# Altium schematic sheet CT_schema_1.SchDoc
size 642 x 258 mm
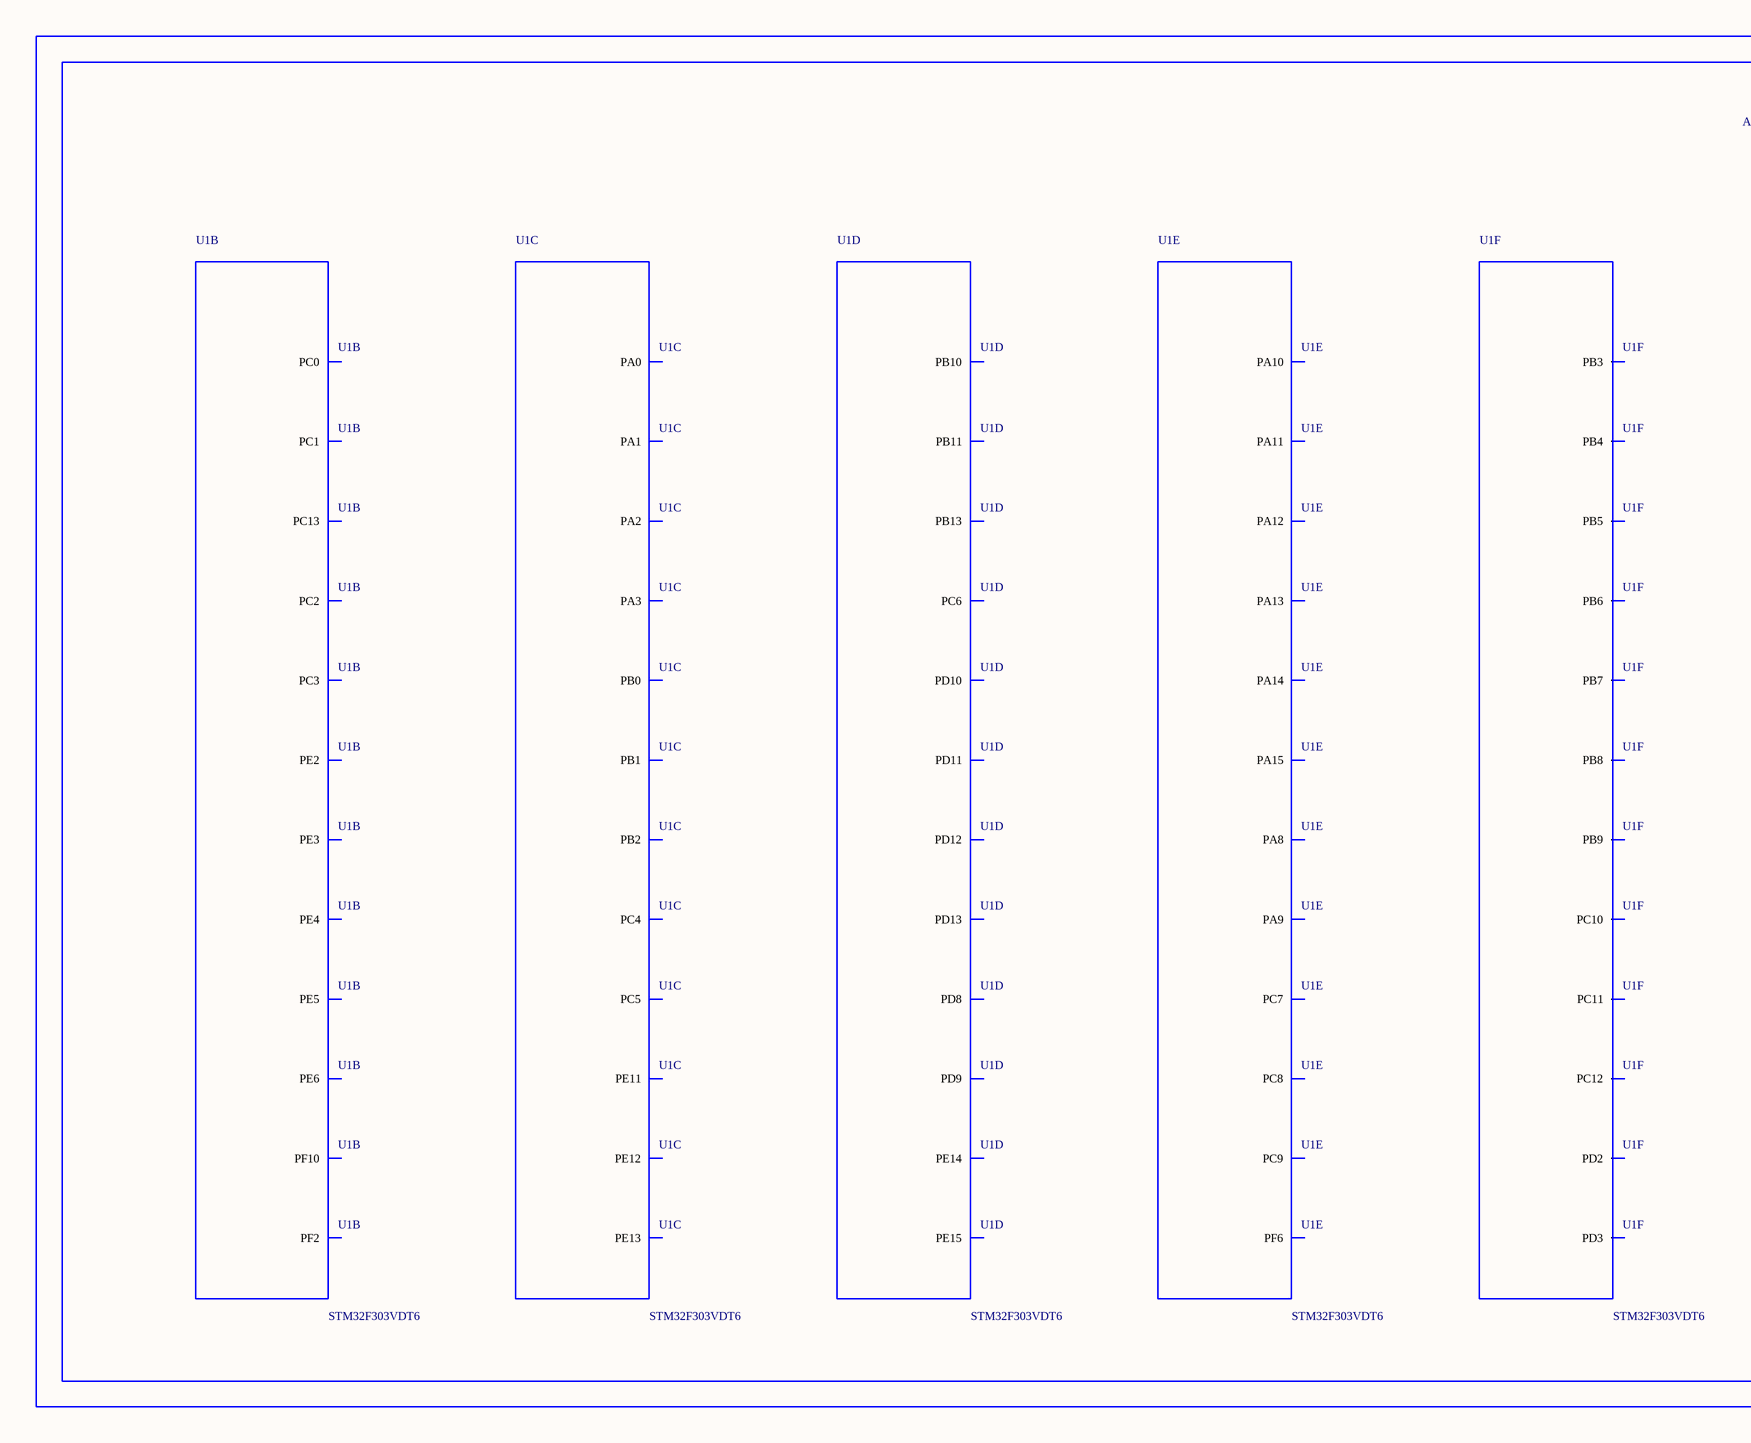
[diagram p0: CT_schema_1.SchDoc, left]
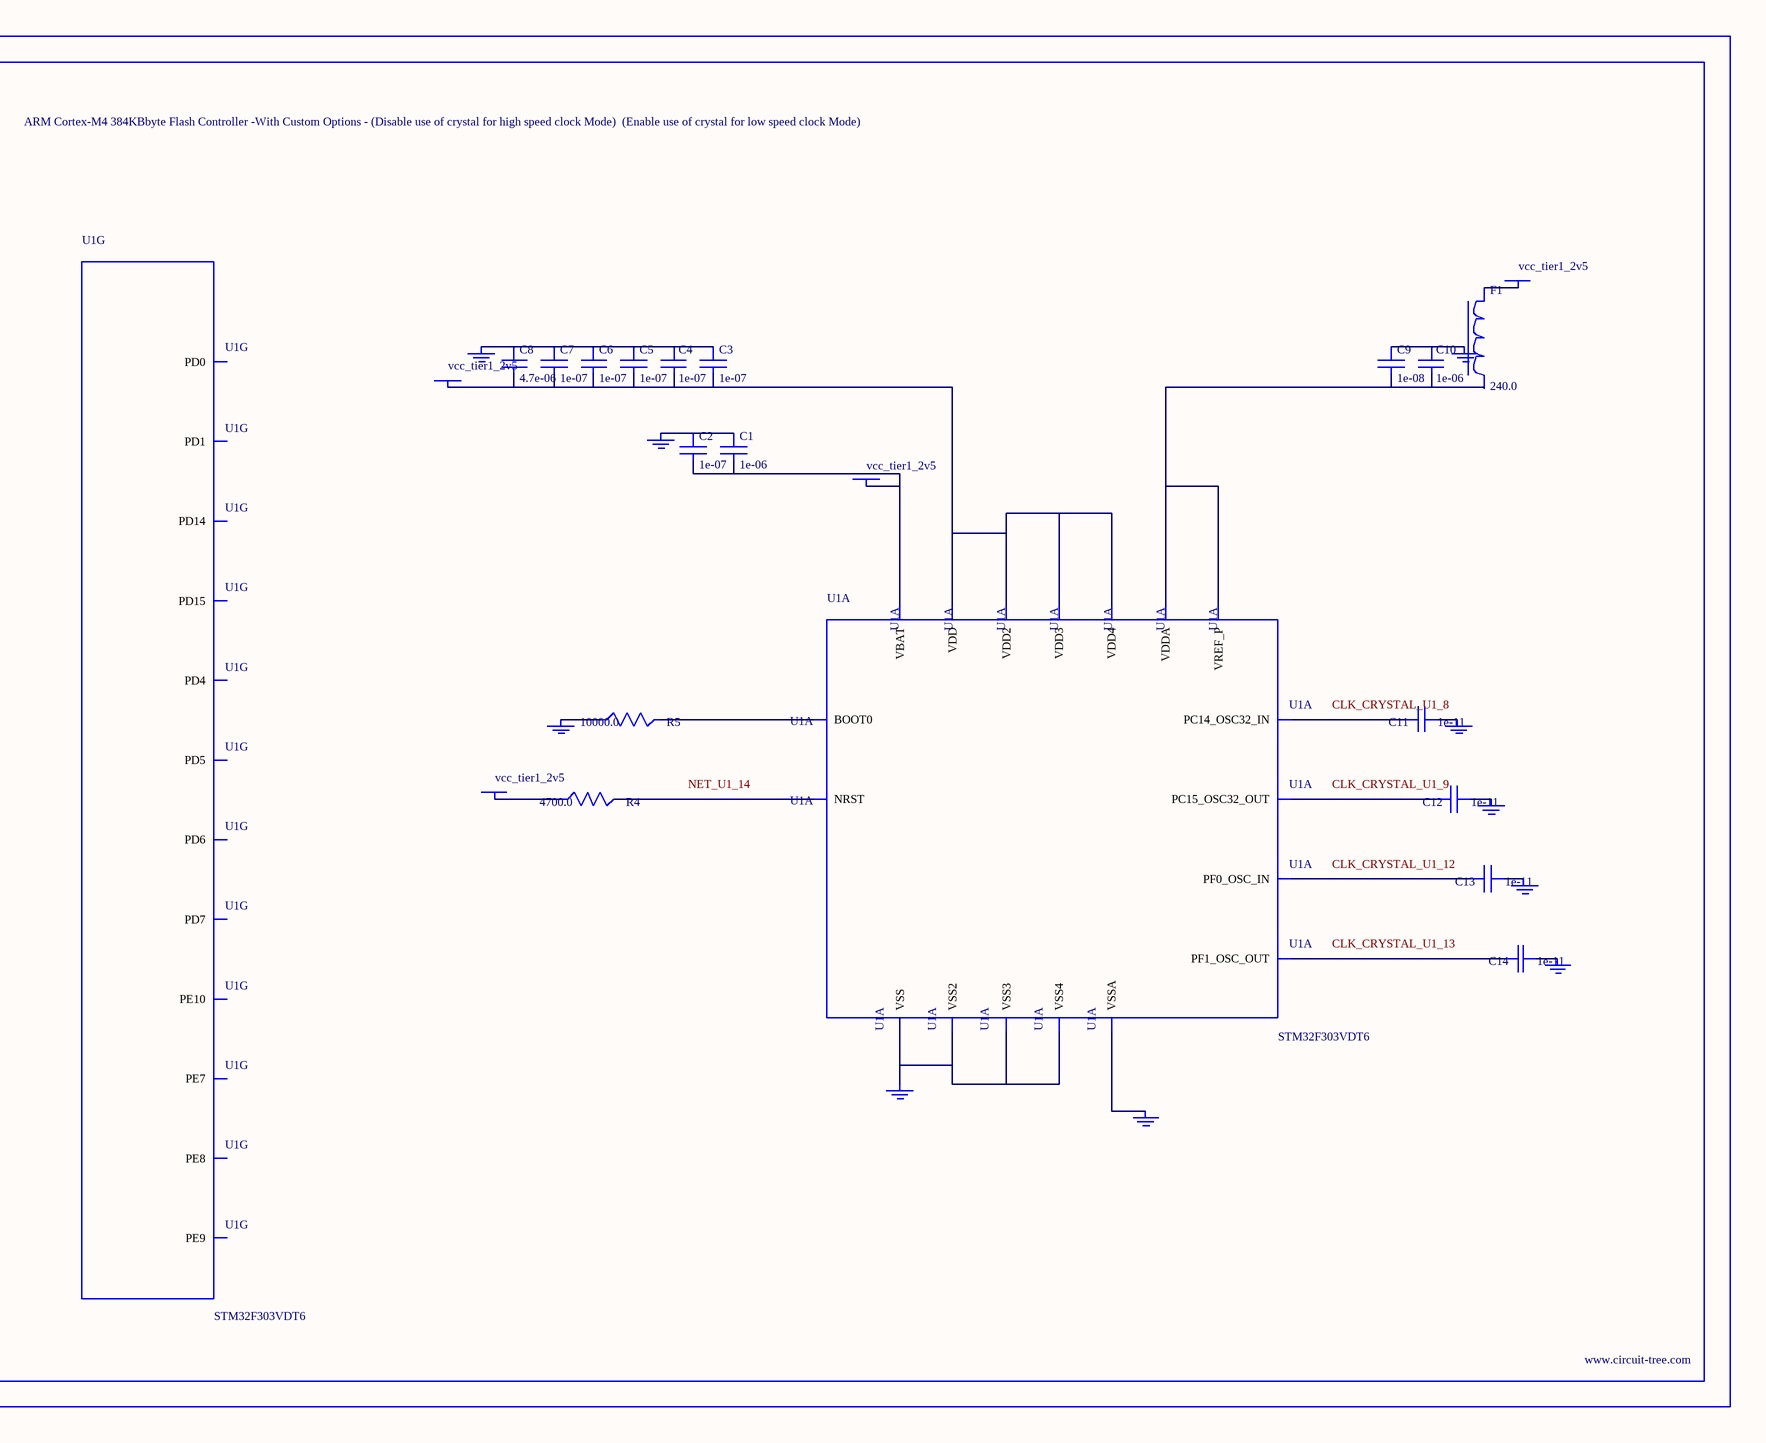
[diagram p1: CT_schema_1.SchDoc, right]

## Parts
BORDER0  (no value)
C1  1e-06  [C0603]
C2  1e-07  [C0603]
C3  1e-07  [C0603]
C4  1e-07  [C0603]
C5  1e-07  [C0603]
C6  1e-07  [C0603]
C7  1e-07  [C0603]
C8  4.7e-06  [C0603]
C9  1e-08  [C0603]
C10  1e-06  [C0603]
C11  1e-11  [C0402]
C12  1e-11  [C0402]
C13  1e-11  [C0402]
C14  1e-11  [C0402]
F1  240.0  [L0603]
GND_INSTANCE_0_0  (no value)
GND_INSTANCE_0_1  (no value)
GND_INSTANCE_0_2  (no value)
GND_INSTANCE_0_3  (no value)
GND_INSTANCE_0_4  (no value)
GND_INSTANCE_0_5  (no value)
GND_INSTANCE_0_6  (no value)
GND_INSTANCE_0_7  (no value)
GND_INSTANCE_0_8  (no value)
GND_INSTANCE_0_9  (no value)
POWER_INSTANCE_0_0  vcc_tier1_2v5
POWER_INSTANCE_0_1  vcc_tier1_2v5
POWER_INSTANCE_0_2  vcc_tier1_2v5
POWER_INSTANCE_0_3  vcc_tier1_2v5
R4  4700.0  [R0603]
R5  10000.0  [R0603]
U1  STM32F303VDT6  [LQFP100]  (parts A,B,C,D,E,F,G of 9)

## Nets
NetC1_1: C1.1 C2.1 GND_INSTANCE_0_0.0(GND)
NetC1_2: C1.2 C2.2 POWER_INSTANCE_0_0.0(PWR) U1.6(VBAT)
NetC3_1: C3.1 C4.1 C5.1 C6.1 C7.1 C8.1 GND_INSTANCE_0_7.0(GND)
NetC3_2: C3.2 C4.2 C5.2 C6.2 C7.2 C8.2 POWER_INSTANCE_0_2.0(PWR) U1.28(VDD) U1.50(VDD2) U1.75(VDD3) U1.100(VDD4)
NetC9_1: C9.1 C10.1 GND_INSTANCE_0_6.0(GND)
NetC9_2: C9.2 C10.2 U1.21(VREF_P) U1.22(VDDA)
NetC11_1: C11.1 GND_INSTANCE_0_1.0(GND)
NetC11_2: C11.2 U1.8(PC14_OSC32_IN)
NetC12_1: C12.1 GND_INSTANCE_0_2.0(GND)
NetC12_2: C12.2 U1.9(PC15_OSC32_OUT)
NetC13_1: C13.1 GND_INSTANCE_0_3.0(GND)
NetC13_2: C13.2 U1.12(PF0_OSC_IN)
NetC14_1: C14.1 GND_INSTANCE_0_4.0(GND)
NetC14_2: C14.2 U1.13(PF1_OSC_OUT)
NetF1_1: F1.1 POWER_INSTANCE_0_1.0(PWR)
NetGND_INSTANCE_0_5_0: GND_INSTANCE_0_5.0(GND) U1.20(VSSA)
NetGND_INSTANCE_0_8_0: GND_INSTANCE_0_8.0(GND) R5.1
NetGND_INSTANCE_0_9_0: GND_INSTANCE_0_9.0(GND) U1.27(VSS) U1.49(VSS2) U1.74(VSS3) U1.99(VSS4)
NetPOWER_INSTANCE_0_3_0: POWER_INSTANCE_0_3.0(PWR) R4.1
NetR4_2: R4.2 U1.14(NRST)
NetR5_2: R5.2 U1.94(BOOT0)

Not connected (* = marked no-connect by the designer): F1 2; U1 1(PE2) 2(PE3) 3(PE4) 4(PE5) 5(PE6) 7(PC13) 11(PF10) 15(PC0) 16(PC1) 17(PC2) 18(PC3) 19(PF2) 23(PA0) 24(PA1) 25(PA2) 26(PA3) 33(PC4) 34(PC5) 35(PB0) 36(PB1) 37(PB2) 38(PE7) 39(PE8) 40(PE9) 41(PE10) 42(PE11) 43(PE12) 44(PE13) 45(PE14) 46(PE15) 47(PB10) 48(PB11) 52(PB13) 55(PD8) 56(PD9) 57(PD10) 58(PD11) 59(PD12) 60(PD13) 61(PD14) 62(PD15) 63(PC6) 64(PC7) 65(PC8) 66(PC9) 67(PA8) 68(PA9) 69(PA10) 70(PA11) 71(PA12) 72(PA13) 73(PF6) 76(PA14) 77(PA15) 78(PC10) 79(PC11) 80(PC12) 81(PD0) 82(PD1) 83(PD2) 84(PD3) 85(PD4) 86(PD5) 87(PD6) 88(PD7) 89(PB3) 90(PB4) 91(PB5) 92(PB6) 93(PB7) 95(PB8) 96(PB9)

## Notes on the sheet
- Labels drawn without touching a wire or pin: CLK_CRYSTAL_U1_8, CLK_CRYSTAL_U1_9, CLK_CRYSTAL_U1_12, CLK_CRYSTAL_U1_13, NET_U1_14

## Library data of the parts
BORDER0 = BORDER_PAGE0
C1 C10 = C0603C105K3RACTU
C2-C7 = 06035C104K4Z2A
C8 = GRM188R6YA475KE15D
C9 = 06035C103K4Z2A
C11-C14 = C0402C100K3GACTU
F1 = Z0603C241ASMST
GND_INSTANCE_0_0-GND_INSTANCE_0_9 = GND
POWER_INSTANCE_0_0-POWER_INSTANCE_0_3 = PWR
R4 = RC0603JR-074K7L
R5 = RC0603JR-0710KL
